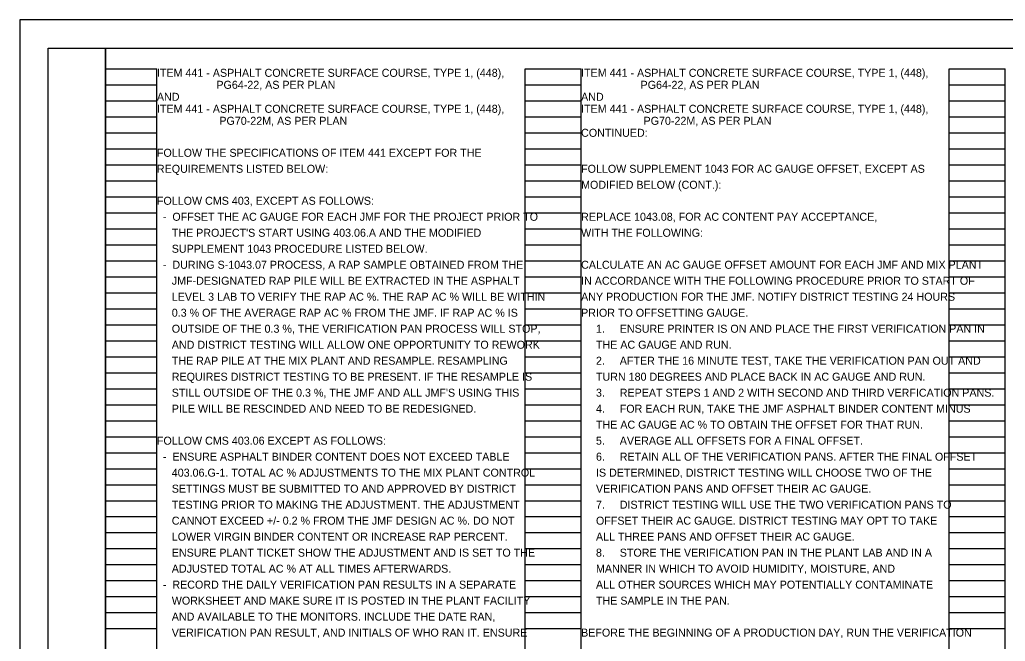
# Model space of a CAD drawing. Extents: x 0 to 34, y 0 to 22.
# Drawn here: x 0 to 17.24, y 11.12 to 22 of the extents above; entities that cross this region are included whole.
import ezdxf

# ---------------------------------------------------------------- set-up
doc = ezdxf.new("R2010")
doc.units = 0
for name, color, linetype in [('SH_Border', 7, 'Continuous'), ('SH_Cut_Line', 7, 'Continuous'), ('SH_Data', 7, 'Continuous'), ('SH_Text', 7, 'Continuous')]:
    doc.layers.add(name, color=color, linetype=linetype)

msp = doc.modelspace()

# ---------------------------------------------------------------- linework, layer by layer
at = {"layer": 'SH_Border'}
for points in [[(0.5, 21.5), (1.5, 21.5), (1.5, 0.5), (0.5, 0.5)], [(1.5, 21.5), (33.5, 21.5), (33.5, 0.5), (1.5, 0.5)]]:
    msp.add_lwpolyline(points, close=True, dxfattribs=at)
at = {"layer": 'SH_Cut_Line'}
msp.add_lwpolyline([(0, 0), (34, 0), (34, 22), (0, 22)], close=True, dxfattribs=at)
at = {"layer": 'SH_Data'}
for p, q in [((1.5, 0.98), (1.5, 21.14)), ((1.5, 21.14), (2.4, 21.14)), ((2.4, 0.98), (2.4, 21.14)), ((8.84, 0.98), (8.84, 21.14)), ((8.84, 21.14), (9.82, 21.14)), ((9.82, 0.98), (9.82, 21.14)), ((16.26, 0.98), (16.26, 21.14)), ((16.26, 21.14), (17.24, 21.14)), ((17.24, 0.98), (17.24, 21.14)), ((1.5, 20.86), (2.4, 20.86)), ((8.84, 20.86), (9.82, 20.86)), ((16.26, 20.86), (17.24, 20.86)), ((1.5, 20.58), (2.4, 20.58)), ((8.84, 20.58), (9.82, 20.58)), ((16.26, 20.58), (17.24, 20.58)), ((1.5, 20.3), (2.4, 20.3)), ((8.84, 20.3), (9.82, 20.3)), ((16.26, 20.3), (17.24, 20.3)), ((1.5, 20.02), (2.4, 20.02)), ((8.84, 20.02), (9.82, 20.02)), ((16.26, 20.02), (17.24, 20.02)), ((1.5, 19.74), (2.4, 19.74)), ((8.84, 19.74), (9.82, 19.74)), ((16.26, 19.74), (17.24, 19.74)), ((1.5, 19.46), (2.4, 19.46)), ((8.84, 19.46), (9.82, 19.46)), ((16.26, 19.46), (17.24, 19.46)), ((1.5, 19.18), (2.4, 19.18)), ((8.84, 19.18), (9.82, 19.18)), ((16.26, 19.18), (17.24, 19.18)), ((1.5, 18.9), (2.4, 18.9)), ((8.84, 18.9), (9.82, 18.9)), ((16.26, 18.9), (17.24, 18.9)), ((1.5, 18.62), (2.4, 18.62)), ((8.84, 18.62), (9.82, 18.62)), ((16.26, 18.62), (17.24, 18.62)), ((1.5, 18.34), (2.4, 18.34)), ((8.84, 18.34), (9.82, 18.34)), ((16.26, 18.34), (17.24, 18.34)), ((1.5, 18.06), (2.4, 18.06)), ((8.84, 18.06), (9.82, 18.06)), ((16.26, 18.06), (17.24, 18.06)), ((1.5, 17.78), (2.4, 17.78)), ((8.84, 17.78), (9.82, 17.78)), ((16.26, 17.78), (17.24, 17.78)), ((1.5, 17.5), (2.4, 17.5)), ((8.84, 17.5), (9.82, 17.5)), ((16.26, 17.5), (17.24, 17.5)), ((1.5, 17.22), (2.4, 17.22)), ((8.84, 17.22), (9.82, 17.22)), ((16.26, 17.22), (17.24, 17.22)), ((1.5, 16.94), (2.4, 16.94)), ((8.84, 16.94), (9.82, 16.94)), ((16.26, 16.94), (17.24, 16.94)), ((1.5, 16.66), (2.4, 16.66)), ((8.84, 16.66), (9.82, 16.66)), ((16.26, 16.66), (17.24, 16.66)), ((1.5, 16.38), (2.4, 16.38)), ((8.84, 16.38), (9.82, 16.38)), ((16.26, 16.38), (17.24, 16.38)), ((1.5, 16.1), (2.4, 16.1)), ((8.84, 16.1), (9.82, 16.1)), ((16.26, 16.1), (17.24, 16.1)), ((1.5, 15.82), (2.4, 15.82)), ((8.84, 15.82), (9.82, 15.82)), ((16.26, 15.82), (17.24, 15.82)), ((1.5, 15.54), (2.4, 15.54)), ((8.84, 15.54), (9.82, 15.54)), ((16.26, 15.54), (17.24, 15.54)), ((1.5, 15.26), (2.4, 15.26)), ((8.84, 15.26), (9.82, 15.26)), ((16.26, 15.26), (17.24, 15.26)), ((1.5, 14.98), (2.4, 14.98)), ((8.84, 14.98), (9.82, 14.98)), ((16.26, 14.98), (17.24, 14.98)), ((1.5, 14.7), (2.4, 14.7)), ((8.84, 14.7), (9.82, 14.7)), ((16.26, 14.7), (17.24, 14.7)), ((1.5, 14.42), (2.4, 14.42)), ((8.84, 14.42), (9.82, 14.42)), ((16.26, 14.42), (17.24, 14.42)), ((1.5, 14.14), (2.4, 14.14)), ((8.84, 14.14), (9.82, 14.14)), ((16.26, 14.14), (17.24, 14.14)), ((1.5, 13.86), (2.4, 13.86)), ((8.84, 13.86), (9.82, 13.86)), ((16.26, 13.86), (17.24, 13.86)), ((1.5, 13.58), (2.4, 13.58)), ((8.84, 13.58), (9.82, 13.58)), ((16.26, 13.58), (17.24, 13.58)), ((1.5, 13.3), (2.4, 13.3)), ((8.84, 13.3), (9.82, 13.3)), ((16.26, 13.3), (17.24, 13.3)), ((1.5, 13.02), (2.4, 13.02)), ((8.84, 13.02), (9.82, 13.02)), ((16.26, 13.02), (17.24, 13.02)), ((1.5, 12.74), (2.4, 12.74)), ((8.84, 12.74), (9.82, 12.74)), ((16.26, 12.74), (17.24, 12.74)), ((1.5, 12.46), (2.4, 12.46)), ((8.84, 12.46), (9.82, 12.46)), ((16.26, 12.46), (17.24, 12.46)), ((1.5, 12.18), (2.4, 12.18)), ((8.84, 12.18), (9.82, 12.18)), ((16.26, 12.18), (17.24, 12.18)), ((1.5, 11.9), (2.4, 11.9)), ((8.84, 11.9), (9.82, 11.9)), ((16.26, 11.9), (17.24, 11.9)), ((1.5, 11.62), (2.4, 11.62)), ((8.84, 11.62), (9.82, 11.62)), ((16.26, 11.62), (17.24, 11.62)), ((1.5, 11.34), (2.4, 11.34)), ((8.84, 11.34), (9.82, 11.34)), ((16.26, 11.34), (17.24, 11.34))]:
    msp.add_line(p, q, dxfattribs=at)

# ---------------------------------------------------------------- texts
at = {"layer": 'SH_Text'}
for s, p in [('ITEM 441 - ASPHALT CONCRETE SURFACE COURSE, TYPE 1, (448),', (2.4, 21)), ('ITEM 441 - ASPHALT CONCRETE SURFACE COURSE, TYPE 1, (448),', (9.82, 21)), ('                    PG64-22, AS PER PLAN', (2.4, 20.79)), ('                    PG64-22, AS PER PLAN', (9.82, 20.79)), ('AND', (2.4, 20.58)), ('AND', (9.82, 20.58)), ('ITEM 441 - ASPHALT CONCRETE SURFACE COURSE, TYPE 1, (448),', (2.4, 20.37)), ('ITEM 441 - ASPHALT CONCRETE SURFACE COURSE, TYPE 1, (448),', (9.82, 20.37)), ('                     PG70-22M, AS PER PLAN', (2.4, 20.16)), ('                     PG70-22M, AS PER PLAN', (9.82, 20.16)), ('CONTINUED:', (9.82, 19.95)), ('FOLLOW THE SPECIFICATIONS OF ITEM 441 EXCEPT FOR THE', (2.4, 19.6)), ('REQUIREMENTS LISTED BELOW:', (2.4, 19.32)), ('FOLLOW SUPPLEMENT 1043 FOR AC GAUGE OFFSET, EXCEPT AS', (9.82, 19.32)), ('MODIFIED BELOW (CONT.):', (9.82, 19.04)), ('FOLLOW CMS 403, EXCEPT AS FOLLOWS:', (2.4, 18.76)), ('  -  OFFSET THE AC GAUGE FOR EACH JMF FOR THE PROJECT PRIOR TO', (2.4, 18.48)), ('REPLACE 1043.08, FOR AC CONTENT PAY ACCEPTANCE,', (9.82, 18.48)), ("     THE PROJECT'S START USING 403.06.A AND THE MODIFIED", (2.4, 18.2)), ('WITH THE FOLLOWING:', (9.82, 18.2)), ('     SUPPLEMENT 1043 PROCEDURE LISTED BELOW.', (2.4, 17.92)), ('  -  DURING S-1043.07 PROCESS, A RAP SAMPLE OBTAINED FROM THE', (2.4, 17.64)), ('CALCULATE AN AC GAUGE OFFSET AMOUNT FOR EACH JMF AND MIX PLANT', (9.82, 17.64)), ('     JMF-DESIGNATED RAP PILE WILL BE EXTRACTED IN THE ASPHALT', (2.4, 17.36)), ('IN ACCORDANCE WITH THE FOLLOWING PROCEDURE PRIOR TO START OF', (9.82, 17.36)), ('     LEVEL 3 LAB TO VERIFY THE RAP AC %. THE RAP AC % WILL BE WITHIN', (2.4, 17.08)), ('ANY PRODUCTION FOR THE JMF. NOTIFY DISTRICT TESTING 24 HOURS', (9.82, 17.08)), ('     0.3 % OF THE AVERAGE RAP AC % FROM THE JMF. IF RAP AC % IS', (2.4, 16.8)), ('PRIOR TO OFFSETTING GAUGE.', (9.82, 16.8)), ('     OUTSIDE OF THE 0.3 %, THE VERIFICATION PAN PROCESS WILL STOP,', (2.4, 16.52)), ('     1.     ENSURE PRINTER IS ON AND PLACE THE FIRST VERIFICATION PAN IN', (9.82, 16.52)), ('     AND DISTRICT TESTING WILL ALLOW ONE OPPORTUNITY TO REWORK', (2.4, 16.24)), ('     THE AC GAUGE AND RUN.', (9.82, 16.24)), ('     THE RAP PILE AT THE MIX PLANT AND RESAMPLE. RESAMPLING', (2.4, 15.96)), ('     2.     AFTER THE 16 MINUTE TEST, TAKE THE VERIFICATION PAN OUT AND', (9.82, 15.96)), ('     REQUIRES DISTRICT TESTING TO BE PRESENT. IF THE RESAMPLE IS', (2.4, 15.68)), ('     TURN 180 DEGREES AND PLACE BACK IN AC GAUGE AND RUN.', (9.82, 15.68)), ("     STILL OUTSIDE OF THE 0.3 %, THE JMF AND ALL JMF'S USING THIS", (2.4, 15.4)), ('     3.     REPEAT STEPS 1 AND 2 WITH SECOND AND THIRD VERFICATION PANS.', (9.82, 15.4)), ('     PILE WILL BE RESCINDED AND NEED TO BE REDESIGNED.', (2.4, 15.12)), ('     4.     FOR EACH RUN, TAKE THE JMF ASPHALT BINDER CONTENT MINUS', (9.82, 15.12)), ('     THE AC GAUGE AC % TO OBTAIN THE OFFSET FOR THAT RUN.', (9.82, 14.84)), ('FOLLOW CMS 403.06 EXCEPT AS FOLLOWS:', (2.4, 14.56)), ('     5.     AVERAGE ALL OFFSETS FOR A FINAL OFFSET.', (9.82, 14.56)), ('  -  ENSURE ASPHALT BINDER CONTENT DOES NOT EXCEED TABLE', (2.4, 14.28)), ('     6.     RETAIN ALL OF THE VERIFICATION PANS. AFTER THE FINAL OFFSET', (9.82, 14.28)), ('     403.06.G-1. TOTAL AC % ADJUSTMENTS TO THE MIX PLANT CONTROL', (2.4, 14)), ('     IS DETERMINED, DISTRICT TESTING WILL CHOOSE TWO OF THE', (9.82, 14)), ('     SETTINGS MUST BE SUBMITTED TO AND APPROVED BY DISTRICT', (2.4, 13.72)), ('     VERIFICATION PANS AND OFFSET THEIR AC GAUGE.', (9.82, 13.72)), ('     TESTING PRIOR TO MAKING THE ADJUSTMENT. THE ADJUSTMENT', (2.4, 13.44)), ('     7.     DISTRICT TESTING WILL USE THE TWO VERIFICATION PANS TO', (9.82, 13.44)), ('     CANNOT EXCEED +/- 0.2 % FROM THE JMF DESIGN AC %. DO NOT', (2.4, 13.16)), ('     OFFSET THEIR AC GAUGE. DISTRICT TESTING MAY OPT TO TAKE', (9.82, 13.16)), ('     LOWER VIRGIN BINDER CONTENT OR INCREASE RAP PERCENT.', (2.4, 12.88)), ('     ALL THREE PANS AND OFFSET THEIR AC GAUGE.', (9.82, 12.88)), ('     ENSURE PLANT TICKET SHOW THE ADJUSTMENT AND IS SET TO THE', (2.4, 12.6)), ('     8.     STORE THE VERIFICATION PAN IN THE PLANT LAB AND IN A', (9.82, 12.6)), ('     ADJUSTED TOTAL AC % AT ALL TIMES AFTERWARDS.', (2.4, 12.32)), ('     MANNER IN WHICH TO AVOID HUMIDITY, MOISTURE, AND', (9.82, 12.32)), ('  -  RECORD THE DAILY VERIFICATION PAN RESULTS IN A SEPARATE', (2.4, 12.04)), ('     ALL OTHER SOURCES WHICH MAY POTENTIALLY CONTAMINATE', (9.82, 12.04)), ('     WORKSHEET AND MAKE SURE IT IS POSTED IN THE PLANT FACILITY', (2.4, 11.76)), ('     THE SAMPLE IN THE PAN.', (9.82, 11.76)), ('     AND AVAILABLE TO THE MONITORS. INCLUDE THE DATE RAN,', (2.4, 11.48)), ('     VERIFICATION PAN RESULT, AND INITIALS OF WHO RAN IT. ENSURE', (2.4, 11.2)), ('BEFORE THE BEGINNING OF A PRODUCTION DAY, RUN THE VERIFICATION', (9.82, 11.2))]:
    msp.add_text(s, height=0.14, dxfattribs=at).set_placement(p)

doc.saveas('drawing.dxf')
